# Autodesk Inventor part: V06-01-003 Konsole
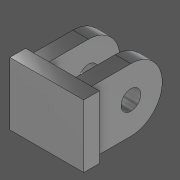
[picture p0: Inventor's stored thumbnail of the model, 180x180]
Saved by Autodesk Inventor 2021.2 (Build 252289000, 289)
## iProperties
RuleStatus: InUse
Company: R-Kon - Rodermund Konstruktion und Entwicklung GmbH
Created: 2020-12
Part Number: V06-01-003 Konsole
Material: Stahl
Document SubType Name: Modeling
Designer: Felix Rodermund
Engineer: Felix Rodermund
Mass: 3071.67 g
Surface Area: 614.577 cm^2
Volume: 391.296 cm^3
Density: 7.85 g/cm^3
Appearance: Stahl
StatusCheck: 1
Title: Teil
Author: Felix Rodermund
Revision Number: 0
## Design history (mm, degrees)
derived "V04-01-000 Gelenkarm Skelett.ipt"
  sketch "yz Armgeometrie"
    geometry: L1 (0, 70.229)-(455.878, 350.229) reference; L2 (455.878, 350.229)-(0, 630.229) reference; L3 (0, -240.046)-(0, 1440.275) reference; L4 (0, 1200.229)-(0, 700.229) reference; L5 (-100, 0.229)-(100, 0.229) reference; L6 (0, 70.229)-(72.973, 600.229) reference; L7 (72.973, 600.229)-(0, 1130.229) reference; L8 (434.944, 384.314)-(-20.935, 104.314) reference; L9 (476.813, 316.145)-(20.935, 36.145) reference; L10 (40, 700.229)-(-40, 700.229) reference; L11 (0, 630.229)-(0, 700.229) reference; L12 (40, 680.229)-(-40, 680.229) reference; L13 (0, 1130.229)-(0, 1200.229) reference; L14 (40, 1200.229)-(-40, 1200.229) reference; A1 r 40 centre (455.878, 350.229) between (476.813, 316.145) and (434.944, 384.314) reference; A2 r 40 centre (0, 70.229) between (20.935, 36.145) and (-20.935, 104.314) reference; 3 further points
    constraints: 1 vertical alignment
  sketch "xz Konsole"
    geometry: L1 (-15, 371.164)-(15, 371.164) reference; L2 (-37, 30.229)-(-17, 30.229) reference; L3 (-47, 57.729)-(47, 57.729) reference; L4 (-47, 82.729)-(-47, 57.729) reference; L5 (47, 82.729)-(-47, 82.729) reference; L6 (47, 70.229)-(-47, 70.229) reference; L7 (47, 700.229)-(-47, 700.229) reference; L8 (-47, 700.229)-(-47, 680.229) reference; L9 (-47, 680.229)-(47, 680.229) reference; L10 (47, 680.229)-(47, 700.229) reference; L11 (-37, 680.229)-(-37, 590.229) reference; L12 (-37, 590.229)-(-17, 590.229) reference; L13 (-17, 590.229)-(-17, 680.229) reference; L14 (15, 670.229)-(-15, 670.229) reference; L15 (-15, 670.229)-(-15, 590.229) reference; L16 (-15, 590.229)-(15, 590.229) reference; L17 (15, 590.229)-(15, 670.229) reference; L18 (0, 670.229)-(0, 590.229) reference; L19 (47, 642.729)-(-47, 642.729) reference; L20 (-47, 642.729)-(-47, 617.729) reference; L21 (-47, 617.729)-(47, 617.729) reference; L22 (47, 617.729)-(47, 642.729) reference; L23 (47, 630.229)-(-47, 630.229) reference; 5 further points
sketch "yz basis"
  geometry: L1 (40, 700.229)-(-40, 700.229) reference; L2 (40, 680.229)-(-40, 680.229) reference; 1 further point
sketch "xz basis"
  geometry: L1 (-47, 700.229)-(-47, 680.229) reference; L2 (47, 700.229)-(-47, 700.229) reference; L3 (-47, 680.229)-(47, 680.229) reference; L4 (47, 680.229)-(47, 700.229) reference; L5 (-17, 590.229)-(-17, 680.229) reference; L6 (-37, 680.229)-(-37, 590.229) reference; L7 (47, 642.729)-(-47, 642.729) reference; L8 (47, 630.229)-(-47, 630.229) reference; L9 (-47, 617.729)-(47, 617.729) reference; L10 (-47, 642.729)-(-47, 617.729) reference; L11 (-37, 590.229)-(-17, 590.229) reference; 1 further point
node "exz unterseite"
sketch "Skizze6"
  geometry: L1 (47, -20)-(-47, -20) reference; L2 (-47, -20)-(-47, 0) reference; L3 (-47, 0)-(47, 0) reference; L4 (47, 0)-(47, -20) reference; 1 further point
extrude "Extrusion1" new body sketch "Skizze6" stored distance "d2" = 10; taper "d3" = 0 deg
node "eyz lasche seite"
sketch "Skizze7"
  geometry: L1 (-40, 90)-(-40, 40); L2 (40, 40)-(40, 90); L3 (40, 90)-(-40, 90); L4 (0, 90)-(0, 0) reference; L5 (-40, 90)-(40, 90) reference; L6 (0, 52.5)-(0, 27.5) reference; A1 r 40 centre (0, 40) between (-40, 40) and (40, 40); 3 further points
  constraints: 6 end point, 3 point on circle, 2 coincident, 2 tangent, 1 centre point, 1 collinear, 1 parallel, 1 perpendicular, 1 vertical, 1 vertical alignment, 2 other
extrude "Extrusion2" new body sketch "Skizze7" stored distance "d4" = 10; taper "d5" = 0 deg
mirror "Spiegeln1"
node "Volumenkörper2"
node "Volumenkörper3"
feature "Anordnung von Volumenkörper3:1"
node "Volumenkörper4"
